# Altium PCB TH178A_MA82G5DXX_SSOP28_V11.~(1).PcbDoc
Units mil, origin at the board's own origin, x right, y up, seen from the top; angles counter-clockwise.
Board outline 2850 x 2110 mil, 2 copper layers (Top Layer, Bottom Layer); 51 components, 47 nets, 262 pads, 128 vias.
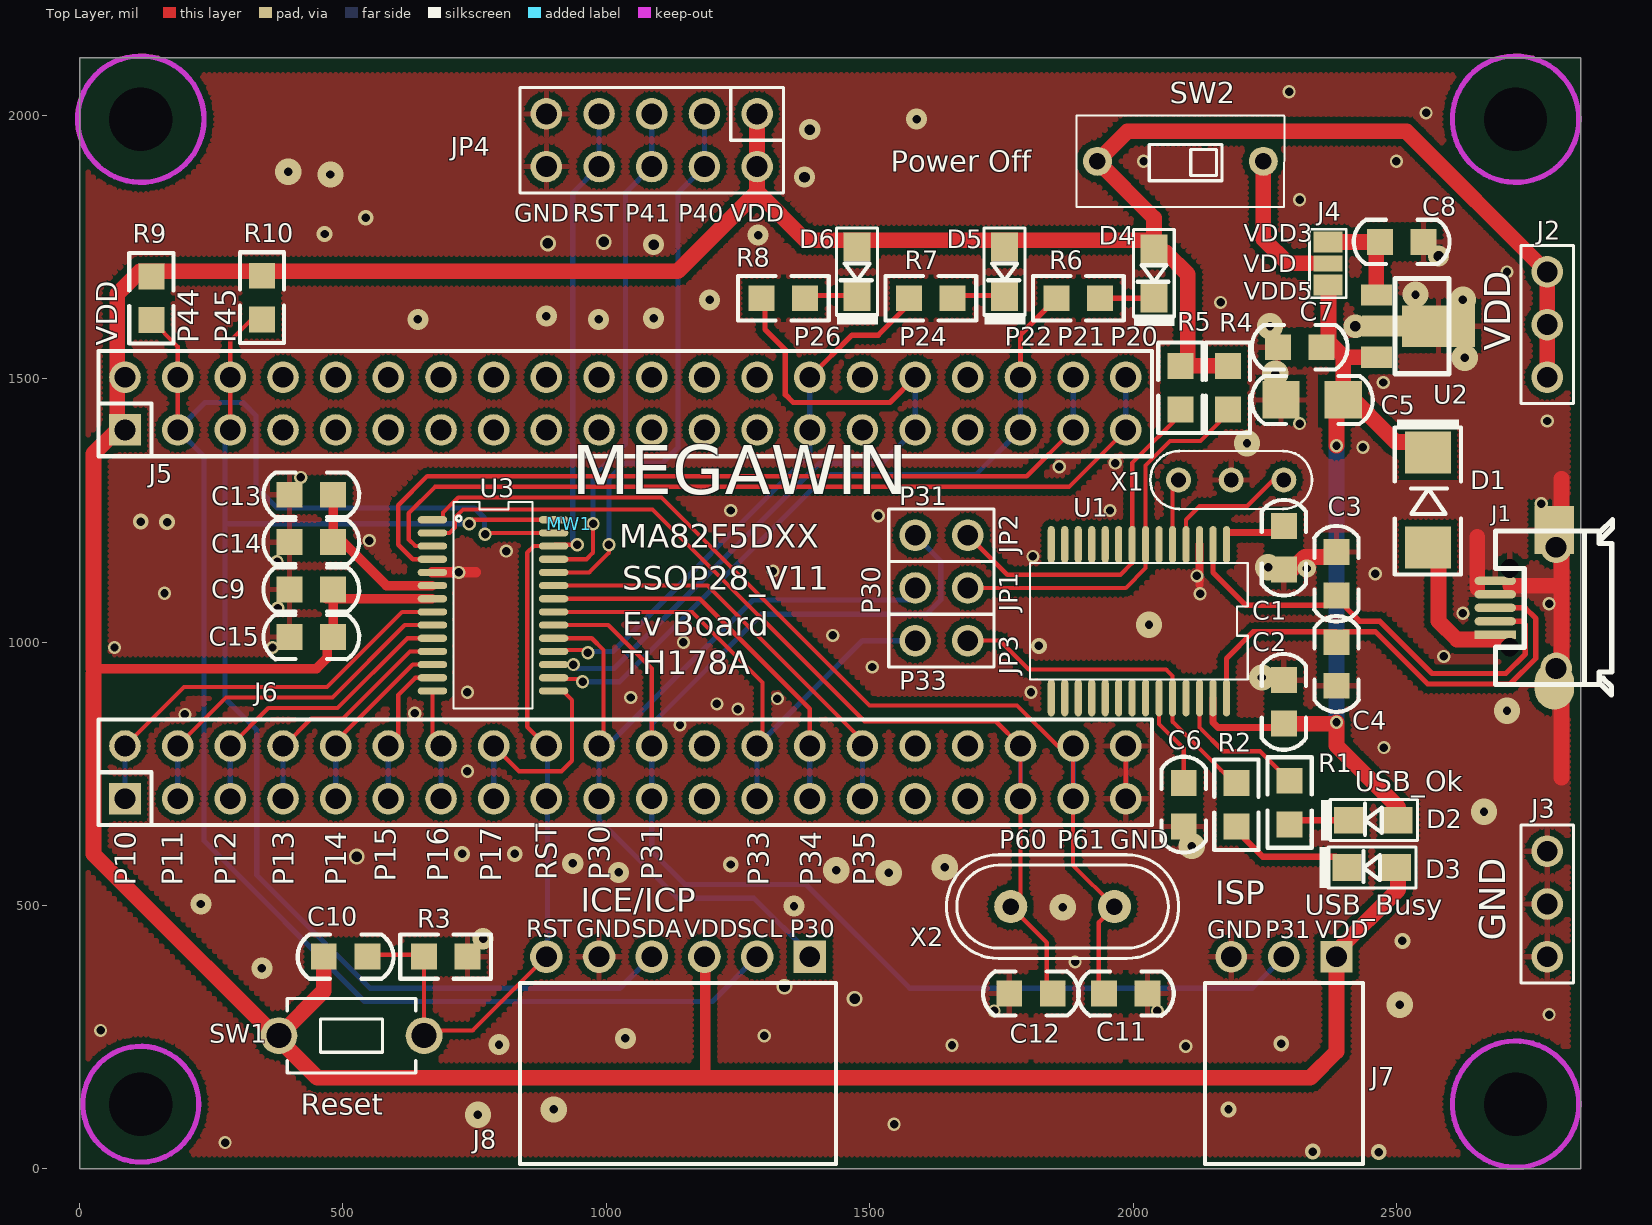
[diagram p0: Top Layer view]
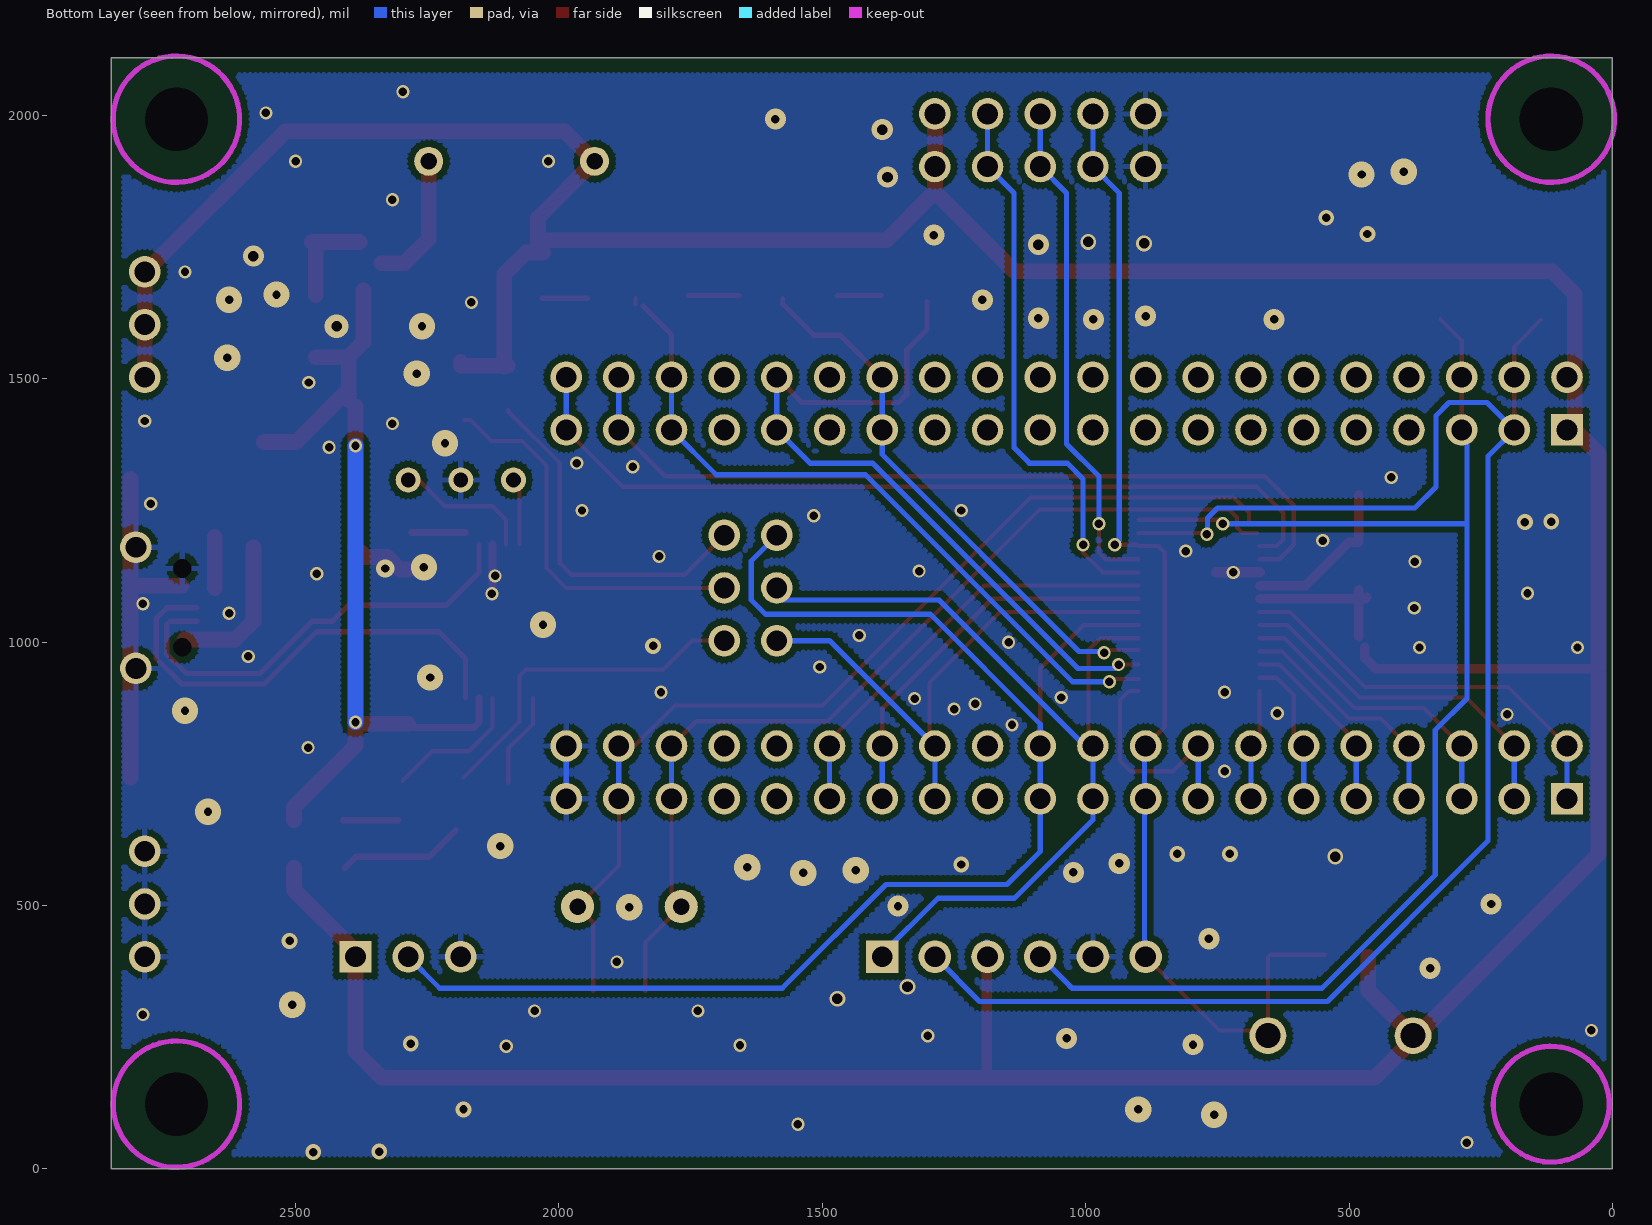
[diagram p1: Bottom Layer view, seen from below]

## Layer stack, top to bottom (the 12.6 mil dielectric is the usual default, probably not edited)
Top Layer: signal copper 1.4
Dielectric: dielectric 12.6, FR-4, Dk 4.8
Bottom Layer: signal copper 1.4

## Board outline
0,0 2850,0 2850,2110 0,2110

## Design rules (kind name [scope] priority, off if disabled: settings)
Clearance 12 [All] p1 off: gap=12
Clearance 10 [All] p2 off: gap=10
Clearance 6 [All] p3: gap=6
ComponentClearance [All] p1 off: gap=10 collisioncheckmode=3 verticalgap=10 showdistances=FALSE
HoleSize [All] p1: absolutevalues=TRUE maxlimit=500 minlimit=1 maxpercent=80.000 minpercent=20.000
MinimumSolderMaskSliver [All] p1 off: minsoldermaskwidth=10
PolygonConnect VIA [ISVIA] p1: connectstyle=Direct reliefconductorwidth=10 reliefentries=4 polygonreliefangle="90 Angle"
PolygonConnect [All] p2: connectstyle=Relief reliefconductorwidth=10 reliefentries=4 polygonreliefangle="90 Angle"
RoutingVias [All] p1: holewidth=16 width=25 viastyle="Through Hole" minholewidth=16 minwidth=24 maxholewidth=28 maxwidth=50
SilkToSilkClearance [All] p1 off: silktosilkclearance=10
SilkscreenOverComponentPads [All] p1 off: minsilkscreentomaskgap=10
SolderMaskExpansion [All] p1 off: expansion=4
Width [All] p1: maxlimit=200 minlimit=6 preferedwidth=10
23 further rules are at their usual default settings.

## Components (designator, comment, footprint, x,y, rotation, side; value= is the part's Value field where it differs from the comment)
C1 "4.7uF" 0805C 2286.34,1179.34 r270 top
C2 "0.1uF" 0805C 2286.34,886.66 r270 top
C3 "15pF" 0805C 2386.34,1130 r90 top
C4 "15pF" 0805C 2386.34,958.66 r270 top
C5 "4.7uF" 1206C 2340,1460 r180 top
C6 "0.1uF" 0805C 2096.34,691.66 r90 top
C7 "0.1uF" 0805C 2316.34,1560 r180 top
C8 "4.7uF" 0805C 2510,1760 r0 top
C9 "0.1uF" 0805C 440,1100 r0 top
C10 "1u" 0805C 505,403 r0 top
C11 "NC" 0805C 1986.34,333 r180 top
C12 "NC" 0805C 1806.34,333 r0 top
C13 "4.7uF" 0805C 440,1280 r180 top
C14 "0.1uF" 0805C 440,1190 r0 top
C15 "NC" 0805C 440,1010 r180 top
D1 "1N5817" D5817_SMD_1 2560,1270 r270 top
D2 "Yellow" 0805D 2456.34,662 r180 top
D3 "Red" 0805D 2453.26,572 r180 top
D4 "Green" 0805D 2040,1700 r270 top
D5 "Red" 0805D 1756.34,1703 r270 top
D6 "Green" 0805D 1476.34,1703 r270 top
J1 "Micro USB母座" JACK_USB_SMD290X220P065 2687.8,1065.28 r180 top
J2 "CON3" PS3P254 2786.34,1503 r90 top
J3 "CON3" PS3P254 2786.34,603 r270 top
J4 "*" JUMP3_SMD 2370,1719 r90 top
J5 "CON40A" PS20X2P254 86.34,1403 r0 top
J6 "CON40A" PS20X2P254 86.34,703 r0 top
J7 "*" PS3P254f_90 2386.34,403 r180 top
J8 "*" PS6P254F_90 1386.34,403 r180 top
JP1 "JUMPER2" PS2P254 1586.34,1103 r0 top
JP2 "JUMPER2" PS2P254 1586.34,1203 r0 top
JP3 "JUMPER2" PS2P254 1586.34,1003 r0 top
JP4 "CON5X2" PS5X2P254 1286.34,2003 r180 top
MW1 "MW-A4" MEGAWIN_T 929.91,1224.43 r0 top
R1 "1K" 0805R 2297.34,695.66 r270 top
R2 "1K" 0805R 2196.34,691.66 r270 top
R3 "47K" 0805R 695,403 r180 top
R4 "4.7K" 0805R 2180,1483 r270 top
R5 "4.7K" 0805R 2090,1483 r270 top
R6 "1K" 0805R 1896.34,1653 r0 top
R7 "1K" 0805R 1616.34,1653 r0 top
R8 "1K" 0805R 1336.34,1653 r0 top
R9 "4.7K" 0805R 136.34,1653 r90 top
R10 "4.7K" 0805R 346.34,1654.34 r90 top
SW1 "SW TACT-SPST" SW_T_2P 516.34,253 r0 top
SW2 "-" DIP2_SW 2247.38,1913 r180 top
U1 "MA101_TSSOP28" SSOP28_220P065 2011.18,1039.85 r180 top
U2 "AIC1734-33(SOT-89)" SOT89 2461.89,1600 r270 top
U3 "MA82F5DXX" SSOP28_150P0635 785,1070 r270 top
X1 "6MHz" X3P 2286.34,1308 r180 top
X2 "NC" X49U 1866.34,498 r180 top

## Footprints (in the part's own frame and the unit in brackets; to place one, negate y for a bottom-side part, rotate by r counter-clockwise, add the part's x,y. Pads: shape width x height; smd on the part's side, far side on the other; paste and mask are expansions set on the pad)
0805C [mm]
  rect 1.25x1.25 smd: 1(-1.05,0) 2(1.05,0)
  silkscreen extent -2.31,-1.07 2.31,1.07
0805D [mm]
  rect 1.4x1.3 smd: 1(-1.192,0) 2(1.192,0)
  silkscreen extent -2.12,-1 2.53,0.98
0805R [mm]
  rect 1.25x1.25 smd: 1(-1.05,0) 2(1.05,0)
  silkscreen extent -2.18,-1.07 2.18,1.07
1206C [mm]
  rect 1.8x1.8 smd: 1(-1.5,0) 2(1.5,0)
  silkscreen extent -2.92,-1.15 2.92,1.16
D5817_SMD_1 [mil]
  rect 80x86.61 smd: 1(90,0) 2(-90,0)
  silkscreen extent -153,-63 142,63
DIP2_SW [mm]
  round 1.4 hole 0.8: 1(0,0) 2(8,0)
  silkscreen extent -1.02,-2.2 9.02,2.2
JACK_USB_SMD290X220P065 [mm]
  rect 1.9x1.8 on Mech2: 0(-2.85,-1.15) 0(-2.85,1.15)
  round 0.8 hole 0.9 unplated: 1(-0.7,1.9) 5(-0.7,-1.9)
  rect 2x0.4 smd: 1(0,1.3)
  oval 2x0.4 smd: 2(0,0.65) 3(0,0) 4(0,-0.65) 5(0,-1.3)
  round 1.524 hole 1: 5(-2.931,2.921) 5(-2.931,-2.921)
  oval 1.9x2.3 smd: 5(-2.85,3.75)
  rect 1.9x2.3 smd: 5(-2.85,-3.75)
  silkscreen extent -5.65,-4.25 -0.01,4.2
JUMP3_SMD [mil]
  rect 40x55 smd: 1(-41,0) 3(41,0)
  rect 30x55 smd: 2(0,0)
  silkscreen extent -65,-35 65,35
MEGAWIN_T [mil]
PS2P254 [mil]
  round 60 hole 39.37: 1(0,0) 2(100,0)
  silkscreen extent -50,-50 150,50
PS3P254 [mil]
  round 60 hole 39.37: 1(0,0) 2(100,0) 3(200,0)
  silkscreen extent -50,-50 250,50
PS3P254f_90 [mil]
  rect 60x60 hole 39.37: 1(0,0)
  round 60 hole 39.37: 2(100,0) 3(200,0)
  silkscreen extent -50,50 250,394
PS5X2P254 [mil]
  round 60 hole 39.37: 1(0,0) 2(0,100) 3(100,0) 4(100,100) 5(200,0) 6(200,100) 7(300,0) 8(300,100) 9(400,0) 10(400,100)
  silkscreen extent -50,-50 450,150
PS6P254F_90 [mil]
  rect 62x62 hole 39.37: 1(0,0)
  round 62 hole 39.37: 2(100,0) 3(200,0) 4(300,0) 5(400,0) 6(500,0)
  silkscreen extent -50,50 550,394
PS20X2P254 [mil]
  rect 60x60 hole 39.37: 1(0,0)
  round 60 hole 39.37: 2(0,100) 3(100,0) 4(100,100) 5(200,0) 6(200,100) 7(300,0) 8(300,100) 9(400,0) 10(400,100) 11(500,0) 12(500,100) 13(600,0) 14(600,100) 15(700,0) 16(700,100) 17(800,0) 18(800,100) 19(900,0) 20(900,100) 21(1000,0) 22(1000,100) 23(1100,0) 24(1100,100) 25(1200,0) 26(1200,100) 27(1300,0) 28(1300,100) 29(1400,0) 30(1400,100) 31(1500,0) 32(1500,100) 33(1600,0) 34(1600,100) 35(1700,0) 36(1700,100) 37(1800,0) 38(1800,100) 39(1900,0) 40(1900,100)
  silkscreen extent -50,-50 1950,150
SOT89 [mm]
  rect 1.016x1.5 smd: 1(-1.5,0) 3(1.5,0)
  rect 2x3.5 smd: 2(0,3)
  rect 1.016x2.6 smd: 2(0,0.6)
  silkscreen extent -2.3,0.9 2.3,3.5
SSOP28_150P0635 [mil]
  oval 13.5x56 smd: 1(-162.5,-115) 2(-137.5,-115) 3(-112.5,-115) 4(-87.5,-115) 5(-62.5,-115) 6(-37.5,-115) 7(-12.5,-115) 8(12.5,-115) 9(37.5,-115) 10(62.5,-115) 11(87.5,-115) 12(112.5,-115) 13(137.5,-115) 14(162.5,-115) 15(162.5,115) 16(137.5,115) 17(112.5,115) 18(87.5,115) 19(62.5,115) 20(37.5,115) 21(12.5,115) 22(-12.5,115) 23(-37.5,115) 24(-62.5,115) 25(-87.5,115) 26(-112.5,115) 27(-137.5,115) 28(-162.5,115)
  silkscreen extent -196,-75 196,75
SSOP28_220P065 [mil]
  oval 13.5x70 smd: 1(-166.34,-145.67) 2(-140.75,-145.67) 3(-115.16,-145.67) 4(-89.57,-145.67) 5(-63.98,-145.67) 6(-38.39,-145.67) 7(-12.79,-145.67) 8(12.8,-145.67) 9(38.39,-145.67) 10(63.98,-145.67) 11(89.57,-145.67) 12(115.16,-145.67) 13(140.75,-145.67) 14(166.34,-145.67) 15(166.34,145.67) 16(140.75,145.67) 17(115.16,145.67) 18(89.57,145.67) 19(63.98,145.67) 20(38.39,145.67) 21(12.8,145.67) 22(-12.79,145.67) 23(-38.39,145.67) 24(-63.98,145.67) 25(-89.57,145.67) 26(-115.16,145.67) 27(-140.75,145.67) 28(-166.34,145.67)
  silkscreen extent -207,-110 207,110
SW_T_2P [mil]
  round 70 hole 47.24: 1(-137.79,0) 2(137.79,0)
  silkscreen extent -122,-71 122,71
X3P [mm]
  round 1.2 hole 0.711: 1(0,0) 2(5.08,0) 3(2.54,0)
  silkscreen extent -1.36,-1.4 6.44,1.4
X49U [mm]
  round 1.6 hole 0.8: 1(-2.5,0) 2(2.5,0)
  silkscreen extent -5.6,-2.5 5.6,2.5

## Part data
C1 C5 C8 C13 C15: library part CAP
C2 C3 C4 C6 C7 C9 C14: library part "CAP NP"
C10: library part C
C11 C12: library part "C NP"
D1: library part DIODE_ZD, "Schottky Diode"
D2 D3 D4 D5 D6: library part LED
J1: library part CON5, "Connector"
J4 J7: library part CON3
J8: library part CON6
R1 R2 R4 R5 R6 R7 R8: library part R_Dup1
R3 R9 R10: library part R
SW2: library part SW-2
U2: library part AIC1734-33(SOT-89)_0
U3: library part MG82FG5Dxx_SSOP-28
X1: library part CRYSTAL_RC
X2: library part CRYSTAL

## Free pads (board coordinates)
  round 40 hole 120 unplated: 0(116.34,123) 0(116.34,1993) 0(2726.34,123) 0(2726.34,1993)

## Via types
v1: diameter 25, hole 16, Top Layer to Bottom Layer, tented both sides, 68 vias
v2: diameter 50, hole 16, Top Layer to Bottom Layer, tented both sides, 21 vias
v3: diameter 40, hole 16, Top Layer to Bottom Layer, tented both sides, 15 vias
v4: diameter 30, hole 16, Top Layer to Bottom Layer, tented both sides, 13 vias
v5: diameter 30, hole 20, Top Layer to Bottom Layer, tented both sides, 5 vias
v6: diameter 40, hole 20, Top Layer to Bottom Layer, tented both sides, 4 vias
v7: diameter 45, hole 20, Top Layer to Bottom Layer, tented both sides, 1 vias
v8: diameter 35, hole 16, Top Layer to Bottom Layer, tented both sides, 1 vias

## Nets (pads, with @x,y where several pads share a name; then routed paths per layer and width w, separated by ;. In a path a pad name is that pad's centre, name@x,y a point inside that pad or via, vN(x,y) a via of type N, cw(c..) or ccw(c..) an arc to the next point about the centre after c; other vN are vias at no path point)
D+: C4.1 J1.3 U1.28 | length 905.3
  Top Layer w10: U1.28 2177.52,969.18 2228.34,1020 C4.1@2375.01,1020 ; C4.1@2386.34,1015.52 2379.49,1015.52 C4.1@2375.01,1020 ; C4.1@2386.34,1020 C4.1@2375.01,1020 ; C4.1@2400,1020 2460,1020 2559.45,920.55 2715.8,920.55 2764.8,969.55 2764.8,1045.2 2744.72,1065.28 J1.3
D-: C3.1 J1.2 U1.2 | length 842.2
  Top Layer w10: U1.2 2151.93,1132.41 2214.34,1070 C3.1@2386.34,1070 ; C3.1@2400,1070 2430,1040 2468.28,1040 2567.73,940.55 2707.51,940.55 2744.8,977.84 2744.8,1033.12 2738.23,1039.69 J1.2
GND_POWER: C1.2 C2.1 C3.2 C4.2 C5.2 C6.1 C7.2 C8.2 C9.1 C11.1 C12.1 C13.2 C14.1 C15.2 J1.4 J1.5 J3.1 J3.2 J3.3 J6.39 J6.40 J7.3 J8.5 JP4.9 JP4.10 R3.1 U1.3 U2.2 U3.5 X1.3 | length 1239.3
  Top Layer w8: J6.39 J6.40
  Top Layer w15: 2126.34,1109 v1@2126.34,1119 ; U1.3 v1@2126.34,1119 ; v1@2127.34,1118 v1@2126.34,1119
  Top Layer w20: U3.5 v1(720,1132.5) 752.5,1132.5
  Top Layer w30: C1.2 2302.34,1138 2326.34,1162 2367.66,1162 C3.2@2386.34,1180.68 ; 2653.66,1102.91 2653.66,1200 ; 2716.34,1107.32 2813.43,1107.32 ; 2813.66,743 2813.66,1310
  Bottom Layer w10: J6.39 J6.40
  other v1: 276.34,50 1546.34,85 2100,233 1656.34,235 1300,253 40,263 2790,293 1736.34,300 2046.34,300 1890,393 736.34,755 2476.34,800 1140,843 200,863 636.34,865 1250,873 1210,883 1325,893 1046.34,895 736.34,905 1806.34,905 1505,953 2590,973 66.34,990 366.34,990 1146.34,1000 1430,1013 2626.34,1055 376.34,1065 2790,1073 2127.34,1092 161.34,1093 2121.34,1126 2460,1130 1316.34,1135 375,1153 1810,1163 810,1173 550,1193 1516.34,1240 1236.34,1250 1956.34,1250 2775,1263 420,1313 1860,1333 1966.34,1340 2436.34,1370 2316.34,1415 2786.34,1420 2475,1493 2166.34,1645 2710,1703 2316.34,1840 2020,1913 2500,1913 2556.34,2005 2296.34,2045
  other v2: 756.34,103 900.34,113 2506.34,312 1866.34,497 1536.34,562 1436.34,567 1642.34,573 2111.34,613 2666.34,678 2710,870 2244.73,933 2030.34,1033 2256.34,1142 2216.34,1378 2270,1510 2630,1540 2260,1600 2626.34,1650 2536.34,1660 476.34,1888 396.34,1893
  other v3: 796.34,236 1036.34,248 346.34,381 766.34,437 1356.34,499 230.34,503 1023.34,563 936.34,580 642.34,1613 985.34,1613 1090,1615 886.34,1619 1196.34,1650 1288.34,1773 1589.34,1993
  other v4: 2466.34,32 2341.34,33 2181.34,113 2281.34,238 2511.34,433 1236.34,578 726.34,598 826.34,598 1821.34,993 166.34,1228 116.34,1229 465.34,1775 543.34,1806
  other v5: 1471.34,323 1338.34,346 526.34,593 889.34,1757 995.34,1760
  other v6: 2580,1733 1090,1755 1376.34,1883 1386.34,1973
  other v7: 2422.33,1600
  other v8: 2330,1140
MA101_RX: JP2.2 R5.2 U1.8 | length 683.4
  Top Layer w8: JP2.2 1761.34,1128 1976.34,1128 1998.39,1150.05 U1.8 1998.39,1340.05 2096.34,1438 R5.2@2096.34,1440.66
MA101_TX: JP1.2 R4.2 U1.7 | length 740
  Top Layer w8: JP1.2 1986.34,1103 2023.98,1140.64 U1.7 2023.98,1335.64 2070.34,1382 2128.34,1382 2168.34,1422 R4.2@2180,1422
NetC1_1: C1.1 U1.1 | length 102.5
  Top Layer w13: U1.1@2177.52,1208 C1.1@2280,1208
NetC6_2: C6.2 U1.23 | length 180.6
  Top Layer w8: U1.23 2049.57,844.77 2096.34,798 C6.2
NetC13_1: C13.1 C14.2 U3.6 | length 312.8
  Top Layer w18: C13.1 C14.2 500,1190 582.5,1107.5 U3.6
NetD1_1: D1.1 J1.1 | length 284.5
  Top Layer w30: D1.1@2580,1180 2580,1040 2615,1005 J1.1@2710,1005
NetD2_2: D2.2 R1.2 | length 104.4
  Top Layer w12: R1.2@2305.01,662 D2.2
NetD3_2: D3.2 R2.2 | length 239.4
  Top Layer w12: R2.2@2196.34,643 2246.34,593 2385.34,593 D3.2
NetD4_2: D4.2 R6.2 | length 85.6
  Top Layer w10: R6.2@1946.34,1653 D4.2@2031.92,1653
NetD5_2: D5.2 R7.2 | length 96.9
  Top Layer w10: R7.2@1657.95,1658 D5.2@1754.87,1658
NetD6_2: D6.2 R8.2 | length 83.8
  Top Layer w10: R8.2@1387.95,1658 D6.2@1471.79,1658
NetJ4_2: J4.2 SW2.1 | length 256.1
  Top Layer w30: SW2.1 2247.38,1765.62 2293.5,1719.5 2337,1719.5
NetU1_4: U1.4 X1.1 | length 263.8
  Top Layer w8: U1.4 2100.75,1232.41 2126.34,1258 2216.34,1258 2266.34,1308 X1.1
NetU1_5: U1.5 X1.2 | length 127.1
  Top Layer w8: U1.5 2075.16,1296.82 X1.2
P10: J6.1 J6.2 U3.8 | length 789.1
  Top Layer w8: J6.2 198.34,915 470,915 612.5,1057.5 U3.8
  Bottom Layer w10: J6.1 J6.2
P11: J6.3 J6.4 U3.9 | length 678.7
  Top Layer w8: J6.4 278.34,895 480,895 617.5,1032.5 U3.9
  Bottom Layer w10: J6.3 J6.4
P12: J6.5 J6.6 U3.10 | length 568.4
  Top Layer w8: J6.6 358.34,875 490,875 622.5,1007.5 U3.10
  Bottom Layer w10: J6.5 J6.6
P13: J6.7 J6.8 U3.11 | length 458
  Top Layer w8: J6.8 388,803 440,855 500,855 627.5,982.5 U3.11
  Bottom Layer w10: J6.7 J6.8
P14: J6.9 J6.10 U3.12 | length 352.5
  Top Layer w8: J6.10 486.34,811.34 632.5,957.5 U3.12
  Bottom Layer w10: J6.9 J6.10
P15: J6.11 J6.12 U3.13 | length 283.2
  Top Layer w8: J6.12 605,821.66 605,900 637.5,932.5 U3.13
  Bottom Layer w10: J6.11 J6.12
P16: J6.13 J6.14 U3.14 | length 188.2
  Top Layer w8: J6.14@670,819.34 U3.14
  Bottom Layer w10: J6.13 J6.14
P17: J6.15 J6.16 U3.15 | length 489.1
  Top Layer w8: J6.16 834.34,755 915,755 935,775 935,790 ; U3.15 917.5,907.5 935,890 935,790 ; 935,845 935,790
  Bottom Layer w10: J6.15 J6.16
P20: J5.39 J5.40 U3.3 | length 1627
  Top Layer w8: U3.3 637.5,1182.5 625,1195 625,1245 675,1295 1878.34,1295 J5.39
  Bottom Layer w10: J5.39 J5.40
P21: J5.37 J5.38 U3.4 | length 1592
  Top Layer w8: U3.4 632.5,1157.5 605,1185 605,1260 660,1315 1798.34,1315 J5.37
  Bottom Layer w10: J5.37 J5.38
P22: J5.35 J5.36 R6.1 U3.16 | length 1353.4
  Top Layer w8: U3.16@900,930 v1@955,930 ; R6.1@1855,1641.66 R6.1
  Top Layer w10: J5.36 1786.34,1584.34 R6.1@1840.37,1638.37
  Bottom Layer w10: v1(955,925) 1025,925 1418,1318 1701.34,1318 J5.35 J5.36
P24: J5.31 J5.32 R8.1 U3.17 | length 1442.2
  Top Layer w8: U3.17 v1(937.5,957.5)
  Top Layer w10: R8.1@1301.34,1646.66 1301.34,1593.66 1340,1555 1340,1470 1355,1455 1538.34,1455 J5.32
  Bottom Layer w10: v1(937.5,957.5) 945,950 1015,950 1405,1340 1523.34,1340 J5.31 J5.32
P26: J5.27 J5.28 R7.1 U3.18 | length 1045.3
  Top Layer w8: U3.18@900,985 v1@965,985 ; R7.1@1575,1641.66 R7.1
  Top Layer w10: J5.28 1466.34,1583 1516.34,1583 R7.1@1575,1641.66
  Bottom Layer w10: v1@965,982.43 1012.43,982.43 1386.34,1356.34 J5.27 J5.28
  other v1: 965,980
P30/RXD: J6.19 J6.20 J8.1 JP1.1 U3.19 | length 1659
  Top Layer w8: U3.19 972.5,1007.5 995,985 995,811.66 J6.20 988.84,800.5 J6.20@988.84,803
  Bottom Layer w10: J6.20@971.34,818 J6.20 J6.19 986.34,663 1135.34,514 1280.34,514 J8.1@1388.34,406 ; J6.20@1001.34,803 1278.34,1080 JP1.1@1580,1080
P31/TXD: J6.21 J6.22 J7.2 JP2.1 U3.20 | length 2751.8
  Top Layer w8: U3.20 1003.78,1032.5 1086.34,949.94 J6.22
  Bottom Layer w10: J6.22@1101.19,788.15 J6.22@1086.34,773.3 ; JP2.1 1635,1154.34 1635,1080 1608,1053 1295,1053 1086.34,844.34 J6.22 J6.22@1086.34,773.3 ; J7.2 2226.34,343 1576.34,343 1379.34,540 1149.34,540 1086.34,603 J6.21 J6.22@1086.34,773.3
P33: J6.25 J6.26 JP3.1 U3.21 | length 1040.4
  Top Layer w8: U3.21 1162.5,1057.5 1296.61,923.39 J6.26@1296.61,803
  Bottom Layer w10: J6.25 J6.26@1286.34,788 ; J6.26 1486.34,1003 JP3.1
P34: J6.27 J6.28 U3.22 | length 743.5
  Top Layer w8: U3.22 1177.5,1082.5 1386.34,873.66 J6.28
  Bottom Layer w10: J6.27 J6.28
P35: J6.29 J6.30 U3.23 | length 818.7
  Top Layer w8: U3.23 1192.5,1107.5 1486.34,813.66 J6.30
  Bottom Layer w10: J6.29 J6.30
P40: JP4.3 JP4.4 U3.24 | length 1070.8
  Top Layer w8: U3.24 967.5,1132.5 1005,1170 v1(1005,1185)
  Bottom Layer w10: v1(1005,1185) 1005,1310 1035,1340 1107,1340 1136.34,1369.34 1136.34,1853 JP4.4 JP4.3
P41: JP4.5 JP4.6 U3.25 | length 967.3
  Top Layer w8: U3.25 962.5,1157.5 975,1170 v1(975,1225)
  Bottom Layer w10: v1(975,1225) 975,1315 1036.34,1376.34 1036.34,1745 ; 1036.34,1753 1036.34,1745 ; JP4.5 JP4.6 1036.34,1853 1036.34,1745
P44: J5.3 J5.4 J8.2 R9.1 U3.27 | length 3233.8
  Top Layer w8: R9.1 186.34,1561.66 J5.4 J5.3 J5.3@186.34,1378 ; v1@762.5,1202.5 767.5,1207.5 U3.27
  Bottom Layer w10: v1@768.6,1205 768.6,1235.97 749.83,1254.74 375.26,1254.74 335,1295 335,1430 310,1455 238.34,1455 J5.3 236.34,1353 236.34,623 541.34,318 1201.34,318 J8.2 ; J8.2@1288.34,403 J8.2@1288.34,426
  other v1: 770,1205
P45: J5.5 J5.6 J8.4 R10.1 U3.28 | length 2685.7
  Top Layer w8: J5.5 J5.6 286.34,1573 R10.1@326.34,1613 ; v1@735,1230 737.5,1232.5 U3.28
  Bottom Layer w10: J5.5 276.34,1393 276.34,1225 ; v1@730,1225 276.34,1225 ; 1029.34,346 J8.4 J8.4@1088.34,405 ; J8.4@1077.84,415.5 J8.4@1088.34,426 ; J8.4@1088.34,406 1025.34,343 551.35,343 336.34,558.01 336.34,833 276.34,893 276.34,1225
  other v1: 740,1225
P60: C12.2 J6.35 J6.36 U3.2 X2.2 | length 1939.5
  Top Layer w8: U3.2@675,1207.5 702.5,1207.5 713,1218 713,1237 728.19,1252.19 820,1252.19 ; 808.47,1252.19 820,1252.19 ; C12.2@1836.34,338 1836.34,429.58 X2.2 1786.34,516.42 J6.35 J6.36 1739.34,850 1490,850 1087.81,1252.19 820,1252.19
  Bottom Layer w10: J6.35 J6.36
P61: C11.2 J6.37 J6.38 U3.1 X2.1 | length 2029.7
  Top Layer w8: U3.1@690,1230 690,1246 719,1275 1105,1275 1500,880 1780,880 1857,803 J6.38 J6.37 1886.34,576.42 X2.1 1935,468.24 C11.2@1935,338
  Bottom Layer w10: J6.37 J6.38
RST: C10.2 J6.17 J6.18 J8.6 JP4.7 JP4.8 R3.2 SW1.2 U3.26 | length 2293.4
  Top Layer w8: C10.2@546.34,406.81 R3.2@649.85,406.81 ; R3.2@654.13,402.53 654.13,263 746.34,263 J8.6 888.34,405 J8.6@888.34,426 ; 850,884.34 850,895 ; J6.18 850,839.34 850,895 ; v1(945,1185) 902.5,1185 U3.26 862.5,1182.5 850,1170 850,895
  Bottom Layer w10: J8.6@888.34,406 J6.18@888.34,801 ; 936.34,1763 936.34,1755 ; v1(945,1185) 936.34,1193.66 936.34,1755 ; JP4.8@981.34,1908 986.34,1913 JP4.7 ; JP4.8 936.34,1853 936.34,1755
USB_BUSY: JP3.2 R2.1 U1.24 | length 782.4
  Top Layer w8: JP3.2 1747,1003 1802,948 2062.95,948 2075.16,935.8 U1.24 2075.16,849.18 ; 2166.34,758 2075.16,849.18 ; R2.1@2181.34,743 2075.16,849.18
USB_OK: R1.1 U1.26 | length 269
  Top Layer w8: U1.26 2126.34,838 2171.34,793 2241.34,793 R1.1
VDD: C9.2 C10.1 C15.1 D3.1 D4.1 D5.1 D6.1 J2.1 J2.2 J2.3 J5.1 J5.2 J7.1 J8.3 JP4.1 JP4.2 R4.1 R5.1 R9.2 R10.2 SW1.1 SW2.2 U3.7 | length 9211.5
  Top Layer w18: 26.34,950 450,950 470,970 C15.1@470,990 ; C9.2@466.34,1085 468.84,1082.5 C9.2@481.34,1082.5 ; C15.1 C9.2@481.34,1082.5 ; C9.2 C9.2@481.34,1082.5 ; U3.7 C9.2@481.34,1082.5
  Top Layer w20: 1188.34,180 J8.3@1188.34,406
  Top Layer w30: 26.34,940 26.34,598 451.34,173 2336.34,173 2386.34,223 J7.1 2386.34,413 2503.26,529.92 D3.1@2503.26,572 ; 26.34,950 26.34,1357.91 71.43,1403 71.43,1660.97 114.79,1704.34 1135.68,1704.34 1286.34,1855 ; SW1.1 463.66,338.12 C10.1 ; SW1.1@382.74,249.56 SW1.1@382.82,252.9 ; JP4.1 JP4.2 1286.34,1855 ; D4.1@2027,1763 1378.34,1763 1286.34,1855 ; D4.1@2030,1740 2062.72,1740 2104,1698.72 R5.1@2104,1524.68 ; D4.1 2040,1805.42 SW2.2 1989.42,1970 2519,1970 J2.3@2786,1703 ; R5.1@2097.68,1524.68 R5.1@2104,1524.68 ; R5.1@2104,1523.68 R5.1@2104,1524.68 ; R4.1@2186.34,1532 2186.34,1524.68 R5.1@2104,1524.68 ; J2.1 J2.2 J2.3@2786.34,1702.66 ; J2.3@2786,1703 J2.3@2786.34,1702.66 ; J2.3@2786,1703 J2.3 J2.3@2786.34,1702.66
  Bottom Layer w20: J8.3@1188.34,405 J8.3@1188.34,426
VDD3: C8.1 J4.3 U2.1 | length 183.8
  Top Layer w30: J4.3@2379,1760 C8.1 ; U2.1 C8.1@2461.89,1753.23
VDD5: C2.2 C5.1 C7.1 D1.2 D2.1 J4.1 U1.27 U2.3 | length 1667.1
  Top Layer w13: U1.27 2151.93,847.41 2161.34,838 2236.34,838 ; 2171.34,838 2236.34,838 ; C2.2@2286.34,838 2236.34,838
  Top Layer w30: C2.2 2383.66,845.32 v1(2386.34,848) 2386.34,803.66 2503.26,686.74 D2.1 ; J4.1@2371.34,1667.66 2371.34,1570 2400.39,1540.94 U2.3 ; v1(2386.34,1373) C5.1@2386.34,1447.28 ; C5.1 C5.1@2399.06,1480 ; 2399.06,1539.61 C5.1@2399.06,1480 ; D1.2@2560,1380 2499.06,1380 C5.1@2399.06,1480
  Bottom Layer w30: v1(2386.34,848) v1(2386.34,1373)
pads on no net: J1.0 J5.7 J5.8 J5.9 J5.10 J5.11 J5.12 J5.13 J5.14 J5.15 J5.16 J5.17 J5.18 J5.19 J5.20 J5.21 J5.22 J5.23 J5.24 J5.25 J5.26 J5.29 J5.30 J5.33 J5.34 J6.23 J6.24 J6.31 J6.32 J6.33 J6.34 U1.6 U1.9 U1.10 U1.11 U1.12 U1.13 U1.14 U1.15 U1.16 U1.17 U1.18 U1.19 U1.20 U1.21 U1.22 U1.25

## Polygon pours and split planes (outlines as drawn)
GND_POWER on Bottom Layer "Bottom Layer-No Net" (hatched 90Degree grid 10 track 10, remove dead copper, pour order 1001): 16.34,27 2826.34,27 2826.34,2078 16.34,2078
GND_POWER on Top Layer "Bottom Layer-No Net" (hatched 90Degree grid 10 track 10, remove dead copper, pour order 1001): 16.34,27 2826.34,27 2826.34,2078 16.34,2078

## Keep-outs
Keep-Out Layer:
  circle w10: c2726.34,123 r120
  circle w10: c116.34,1993 r120
  circle w10: c116.34,123 r110
  circle w10: c2726.34,1993 r120

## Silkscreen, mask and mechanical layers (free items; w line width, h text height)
Top Overlay:
  text "Power Off" at 1540,1893 h40
  text "GND" at 825.34,1798 h33
  text "RST" at 936.34,1798 h33
  text "P41" at 1036.34,1798 h33
  text "P40" at 1136.34,1798 h33
  text "VDD" at 1236.34,1798 h33
  text "VDD3" at 2210,1760 h33
  text "VDD" at 2209.58,1702 h33
  text "VDD5" at 2210,1650 h33
  text "P44" at 226.34,1568 h40 r90
  text "P45" at 296.34,1568 h40 r90
  text "VDD" at 71.34,1563 h40 r90
  text "P26" at 1356.34,1563 h35
  text "P24" at 1556.34,1563 h35
  text "P22" at 1756.34,1563 h35
  text "P21" at 1856.34,1563 h35
  text "P20" at 1956.34,1563 h35
  text "VDD" at 2716.34,1553 h50 r90
  text "P31" at 1556.34,1260 h35
  text "MA82F5DXX" at 1024.91,1179.43 h45
  text "SSOP28_V11" at 1029.91,1099.43 h45
  text "P30" at 1520,1053 h35 r90
  text "Ev Board" at 1029.91,1011.93 h45
  text "TH178A" at 1029.91,939.43 h45
  text "P33" at 1556.34,910 h35
  text "USB_Ok" at 2421.34,717 h38
  text "P60" at 1746.34,608 h35
  text "P61" at 1856.34,608 h35.43
  text "GND" at 1956.34,608 h35.43
  text "RST" at 906.34,548 h40 r90
  text "P30" at 1006.34,548 h40 r90
  text "P31" at 1106.34,548 h40 r90
  text "P15" at 600.29,544.95 h40 r90
  text "P16" at 700.29,544.95 h40 r90
  text "P17" at 800.29,544.95 h40 r90
  text "P10" at 106.34,538 h40 r90
  text "P11" at 196.34,538 h40 r90
  text "P12" at 296.34,538 h40 r90
  text "P13" at 406.34,538 h40 r90
  text "P14" at 506.34,538 h40 r90
  text "P33" at 1308.34,538 h40 r90
  text "P34" at 1408.34,538 h40 r90
  text "P35" at 1508.34,538 h40 r90
  text "ISP" at 2156.34,503 h45
  text "ICE/ICP" at 951.34,488 h45
  text "USB_Busy" at 2326.34,483 h38
  text "RST" at 848.34,440 h33
  text "GND" at 943.34,440 h33
  text "SDA" at 1048.34,440 h33
  text "VDD" at 1148.34,440 h33
  text "SCL" at 1248.34,440 h33
  text "P30" at 1348.34,440 h33
  text "GND" at 2141.34,438 h33
  text "P31" at 2251.34,438 h33
  text "VDD" at 2346.34,438 h33
  text "GND" at 2706.34,433 h50 r90
  text "Reset" at 420,103 h40
Mechanical 1:
  the board outline again, w13
Mechanical 2:
  lines w6: -53.66,303 86.34,303 ; 386.34,2003 386.34,2143 ; 1286.34,2003 1286.34,2143 ; 1486.34,2003 1486.34,2143 ; 2386.34,2003 2386.34,2143 ; 2786.34,603 2926.34,603 ; 2786.34,1503 2926.34,1503

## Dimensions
0,2110 to 0,0 on Top Overlay
0,0 to 2850,0 on Top Overlay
